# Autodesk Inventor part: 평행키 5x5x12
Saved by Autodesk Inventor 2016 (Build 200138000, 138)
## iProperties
Created: 2024-08
Part Number: 평행키 5x5x12
Material: 일반
Description: 키 및 해당 키홈
Document SubType Name: Modeling
Designer: pc-2
Density: 1 g/cm^3
Appearance: 기본값
Author: jhkim
Sending System: Autodesk Inventor 2025
Preprocessor: ST-DEVELOPER v20
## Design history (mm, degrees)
node "평행키 5x5x121"
node "솔리드1"
body "Solid1"
